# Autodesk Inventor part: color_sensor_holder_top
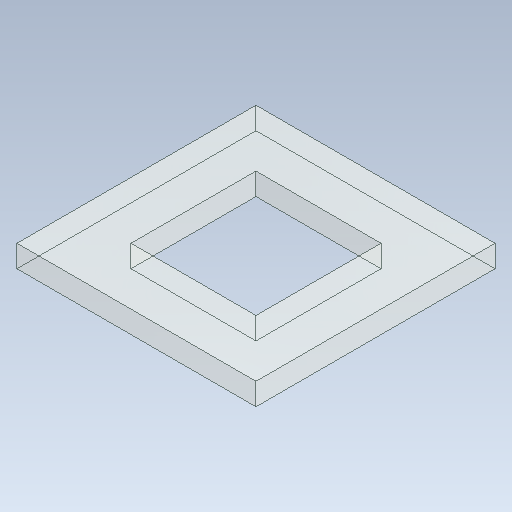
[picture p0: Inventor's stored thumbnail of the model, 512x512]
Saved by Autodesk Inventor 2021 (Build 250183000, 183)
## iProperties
Created: 2026-10
Part Number: color_sensor_holder_top
Material: Generic
Document SubType Name: Modeling
Designer: alolo
Density: 1 g/cm^3
Appearance: Clear
Author: alolo
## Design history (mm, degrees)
sketch "Sketch1"
  geometry: L1 (0, 0)-(-65, 0); L2 (-65, 0)-(-65, 65); L3 (-65, 65)-(0, 65); L4 (0, 65)-(0, 0); L5 (-15.5, 15.5)-(-49.5, 15.5); L6 (-49.5, 15.5)-(-49.5, 49.5); L7 (-49.5, 49.5)-(-15.5, 49.5); L8 (-15.5, 49.5)-(-15.5, 15.5); 4 further points
  constraints: 16 end point, 4 midpoint, 4 parallel, 4 perpendicular, 2 horizontal, 1 horizontal alignment, 1 vertical alignment
  dimensions: "d0" = 65 distance of L2.end L3.end (= slide_width); "d4" = 34 distance of L6.end L7.end
extrude "Extrusion1" new body sketch "Sketch1" distance "d2" = 6 (= aclyric_thickness); taper "d3" = 0 deg
body "Solid1"
other parameters: "slide_length" = 195 [user parameter], "slide_angle" = 7 deg [user parameter], "slide_width" = 65 [user parameter; used in 1 equation term], "wood_thickness" = 5 [user parameter], "aclyric_thickness" = 6 [user parameter; used in 1 equation term]
